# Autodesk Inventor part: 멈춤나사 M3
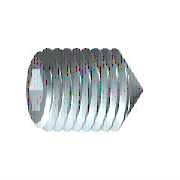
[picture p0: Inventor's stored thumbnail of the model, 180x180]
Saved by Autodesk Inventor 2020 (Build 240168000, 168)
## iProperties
Created: 2012-02
Part Number: 멈춤나사 M3
Material: 강철, 연강
Description: 6각 소켓 머리 없는 멈춤 나사
Document SubType Name: Modeling
Standard: KS B 1028
Designer: test
Standards Organization: KS
Language: ko-KR
Size Designation: 원추점 M3x8
Categories: <MemberInstance><Categories><Category DisplayName="조임쇠" InternalName="e4da775c-781d-43d5-af7c-5136215cf5a6" Mnemonic="FSTN"><Category DisplayName="볼트" InternalN
Density: 1 g/cm^3
Appearance: 강철
IsCustomPart: 1
Author: test
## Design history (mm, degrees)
sketch "스케치1"
  geometry: L1 (0, 0)-(5.5, 0); L2 (8, 0.866)-(8, 1.5); L3 (8, 1.5)-(0, 1.5); L4 (8, 0.866)-(6, 0.866); L5 (6, 0.866)-(5.5, 0); L6 (0, -0.3)-(0, 1.8) reference; L7 (0, 1.5)-(0, 0)
  constraints: 13 end point, 3 parallel, 1 collinear, 1 perpendicular, 1 point on line
  dimensions: "d0" = 2 distance of L2.start L4.end (= INTI); "d1" = 60 deg angle of L5 L1; "d2" = 3 diameter of L3 L1 (= NND); "d3" = 1.73205 diameter of L4 L1 (= 1.1547 x SW); "d5" = 8 distance from line of L2 L3.end (= NLG)
revolve "본체" sketch "스케치1" stored, may be unused: angle "d6" = 90 deg
sketch "스케치2"
  geometry: L1 (-0.433, 0.75)-(0.433, 0.75); L2 (0.433, 0.75)-(0.866, 0); L3 (0.866, 0)-(0.433, -0.75); L4 (0.433, -0.75)-(-0.433, -0.75); L5 (-0.433, -0.75)-(-0.866, 0); L6 (-0.866, 0)-(-0.433, 0.75); 3 further points
  constraints: 12 end point, 1 coincident, 1 horizontal, 13 other
extrude "슬롯" join sketch "스케치2" taper "d7" = 0 deg; stored distance "d21" = 10
workaxis "Work Axis1"
workplane "Work Plane1"
sketch "스케치4"
  geometry: L1 (0, 0.15)-(-1.35, 1.5) reference; L2 (0, -0.15)-(-1.35, -1.5) reference; L3 (-1.35, -1.5)-(0.15, 0); L4 (-1.35, 1.5)-(0.15, 0); 2 further points
  constraints: 4 end point, 1 coincident, 1 collinear, 1 horizontal alignment
body "Solid1"
feature "스레드" dims "d12" = 8 (= NLG), "d13" = 0
chamfer "모따기1" distance "d8" = 1.35 (computed from NND, SPD, FAWI); stored, may be unused: angle "d9" = 45 deg (= FAWI), second distance "d34" = 1.35 (computed from NND, SPD, FAWI)
chamfer "모따기2" distance "d10" = 0.30673 (= -0.5 x GD1 + 0.5 x NND); stored, may be unused: angle "d11" = 45 deg (= FAWI), second distance "d35" = 0.30673 (= -0.5 x GD1 + 0.5 x NND)
other parameters: "NND" = 3 [user parameter; used in 5 equation terms], "NLG" = 8 [user parameter; used in 2 equation terms], "INTI" = 2 [user parameter; used in 1 equation term], "FAWI" = 45 deg [user parameter; used in 4 equation terms], "SW" = 1.5 [user parameter; used in 2 equation terms], "GD1" = 2.38655 (= THREADDIA - 1.2269 x PTC) [user parameter; used in 2 equation terms], "d4" = 0, "FAWI1" = 45 deg [user parameter], "SPD" = 0.3 [user parameter; used in 2 equation terms], "d36" = 0, "d37" = 0, "GUL" = 0.30673 (= 0.61345 x PTC) [user parameter], "TOA" = 30 deg [user parameter], "THREADDIA" = 3 [user parameter; used in 1 equation term], "PTC" = 0.5 [user parameter; used in 4 equation terms], "GAL" = 0.30673 (= 0.61345 x PTC) [user parameter], "E0" = 1.7325 (= 1.155 x SW) [user parameter]
